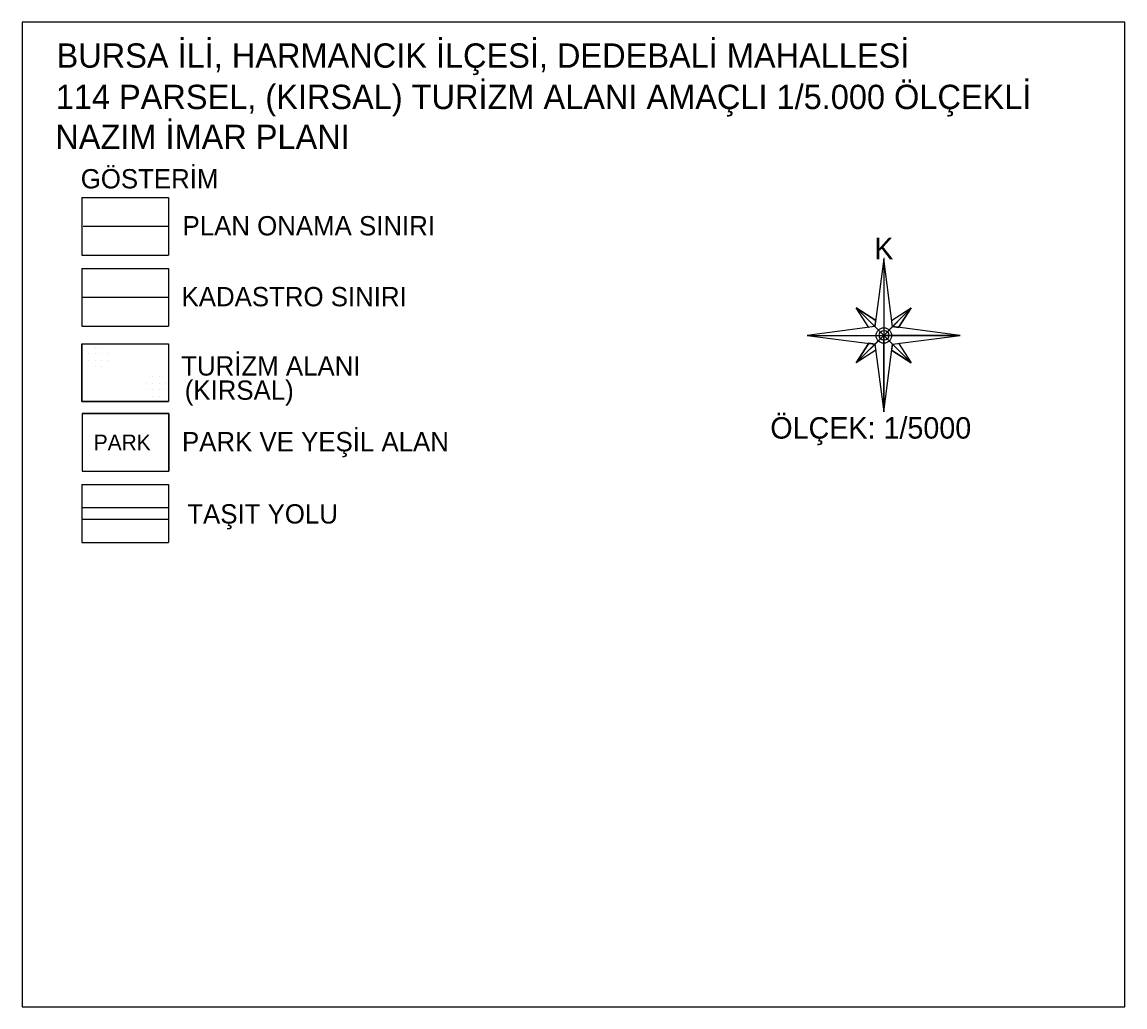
# Model space of a CAD drawing. Extents: x 415376 to 421084, y 4391163 to 4393878.
# Drawn here: x 420706.1 to 421084, y 4391162.7 to 4391500.1 of the extents above; entities that cross this region are included whole.
import ezdxf

# ---------------------------------------------------------------- set-up
doc = ezdxf.new("R2010")
doc.units = 0
for name, color, linetype in [('KALDIRIM', 7, 'Continuous'), ('LEJAND', 7, 'Continuous'), ('PL_KiRSALTURIZM', 7, 'Continuous'), ('PL_PARK', 7, 'Continuous'), ('SN_PLAN_ONAMA', 7, 'Continuous'), ('TR_TURIZM', 7, 'Continuous'), ('Z_PARSEL_PL', 7, 'Continuous')]:
    doc.layers.add(name, color=color, linetype=linetype)

msp = doc.modelspace()

# ---------------------------------------------------------------- linework, layer by layer
at = {"layer": 'KALDIRIM'}
for p, q in [((420726.6, 4391333.76), (420734.34, 4391333.76)), ((420734.34, 4391333.76), (420756.28, 4391333.76)), ((420726.6, 4391329.84), (420734.57, 4391329.84)), ((420734.57, 4391329.84), (420756.28, 4391329.84))]:
    msp.add_line(p, q, dxfattribs=at)
at = {"layer": 'LEJAND'}
for p, q in [((421084.04, 4391500.11), (420706.14, 4391500.11)), ((420706.14, 4391500.11), (420706.14, 4391162.72)), ((421084.04, 4391162.72), (421084.04, 4391500.11)), ((420726.6, 4391440.03), (420726.6, 4391420.21)), ((420726.6, 4391440.03), (420756.33, 4391440.03)), ((420756.33, 4391440.03), (420756.33, 4391420.21)), ((420726.6, 4391420.21), (420756.33, 4391420.21)), ((421001.37, 4391419.02), (421001.37, 4391392.79)), ((421001.59, 4391419.3), (421001.59, 4391419.25)), ((420726.6, 4391415.72), (420756.33, 4391415.72)), ((420726.6, 4391415.72), (420726.6, 4391395.9)), ((420756.33, 4391415.72), (420756.33, 4391395.9)), ((421001.37, 4391392.79), (420991.98, 4391402.18)), ((421001.37, 4391392.79), (421010.76, 4391402.18)), ((420726.6, 4391395.9), (420756.33, 4391395.9)), ((420726.6, 4391389.91), (420726.6, 4391370.1)), ((420726.6, 4391389.91), (420756.33, 4391389.91)), ((420756.33, 4391389.91), (420756.33, 4391370.1)), ((420975.15, 4391392.79), (421001.37, 4391392.79)), ((421001.37, 4391392.79), (420991.98, 4391383.4)), ((421001.37, 4391392.79), (421001.37, 4391366.57)), ((421001.37, 4391392.79), (421010.76, 4391383.4)), ((421001.37, 4391392.79), (421027.6, 4391392.79)), ((420726.6, 4391370.1), (420756.33, 4391370.1)), ((420726.76, 4391366.03), (420726.76, 4391346.21)), ((420726.76, 4391366.03), (420756.49, 4391366.03)), ((420756.49, 4391366.03), (420756.49, 4391346.21)), ((420726.76, 4391346.21), (420756.49, 4391346.21)), ((420726.6, 4391341.7), (420726.6, 4391321.88)), ((420726.6, 4391341.7), (420756.33, 4391341.7)), ((420756.33, 4391341.7), (420756.33, 4391321.88)), ((420726.6, 4391321.88), (420756.33, 4391321.88)), ((420706.14, 4391162.72), (421084.04, 4391162.72))]:
    msp.add_line(p, q, dxfattribs=at)
for points in [[(421004.36, 4391395.78), (421001.37, 4391419.02), (420998.39, 4391395.78), (420975.15, 4391392.79), (420998.39, 4391389.81), (421001.37, 4391366.57), (421004.36, 4391389.81), (421027.6, 4391392.79)], [(421001.37, 4391419.02), (421001.37, 4391392.79), (421004.36, 4391395.78)], [(420991.98, 4391402.18), (420998.39, 4391395.78), (420998.65, 4391397.86)], [(421004.36, 4391395.78), (421006.44, 4391395.51), (421010.76, 4391402.18)], [(420998.39, 4391395.78), (420975.17, 4391392.79), (421001.37, 4391392.79)], [(420996.31, 4391390.07), (420991.98, 4391383.4), (420998.39, 4391389.81)], [(421001.37, 4391392.79), (420998.39, 4391389.81), (421001.37, 4391366.57)], [(421001.37, 4391392.79), (421004.36, 4391389.81), (421027.6, 4391392.79)], [(421004.36, 4391389.81), (421004.09, 4391387.73), (421010.76, 4391383.4)]]:
    msp.add_lwpolyline(points, close=True, dxfattribs=at)
for points in [[(420996.31, 4391395.51), (420991.98, 4391402.18), (420998.65, 4391397.86)], [(421004.09, 4391397.86), (421010.76, 4391402.18), (421006.44, 4391395.51)], [(420998.65, 4391387.73), (420991.98, 4391383.4), (420996.31, 4391390.07)], [(421006.44, 4391390.07), (421010.76, 4391383.4), (421004.09, 4391387.73)]]:
    msp.add_lwpolyline(points, dxfattribs=at)
for centre, radius in [((421001.42, 4391392.73), 2.66), ((421001.46, 4391392.78), 1.66)]:
    msp.add_circle(centre, radius, dxfattribs=at)
at = {"layer": 'PL_KiRSALTURIZM'}
msp.add_lwpolyline([(420756.33, 4391389.91), (420756.33, 4391370.1), (420726.6, 4391370.1), (420726.6, 4391389.91)], close=True, dxfattribs=at)
at = {"layer": 'PL_PARK'}
msp.add_lwpolyline([(420756.49, 4391366.03), (420726.76, 4391366.03), (420726.76, 4391346.21), (420756.49, 4391346.21), (420756.49, 4391366.03)], dxfattribs=at)
at = {"layer": 'SN_PLAN_ONAMA'}
msp.add_line((420727.1, 4391430.23), (420756.16, 4391430.23), dxfattribs=at)
at = {"layer": 'TR_TURIZM'}
for p, q in [((420728.94, 4391386.4), (420728.94, 4391386.4)), ((420731.14, 4391388.6), (420731.14, 4391388.6)), ((420731.14, 4391386.4), (420731.14, 4391386.4)), ((420733.35, 4391388.6), (420733.35, 4391388.6)), ((420733.35, 4391386.4), (420733.35, 4391386.4)), ((420735.55, 4391386.4), (420735.55, 4391386.4)), ((420728.94, 4391384.19), (420728.94, 4391384.19)), ((420731.14, 4391384.19), (420731.14, 4391384.19)), ((420731.14, 4391381.99), (420731.14, 4391381.99)), ((420733.35, 4391384.19), (420733.35, 4391384.19)), ((420733.35, 4391381.99), (420733.35, 4391381.99)), ((420735.55, 4391384.19), (420735.55, 4391384.19)), ((420750.95, 4391378.53), (420750.95, 4391378.53)), ((420753.15, 4391378.53), (420753.15, 4391378.53)), ((420748.74, 4391376.33), (420748.74, 4391376.33)), ((420750.95, 4391376.33), (420750.95, 4391376.33)), ((420753.15, 4391376.33), (420753.15, 4391376.33)), ((420755.36, 4391376.33), (420755.36, 4391376.33)), ((420748.74, 4391374.12), (420748.74, 4391374.12)), ((420750.95, 4391374.12), (420750.95, 4391374.12)), ((420750.95, 4391371.92), (420750.95, 4391371.92)), ((420753.15, 4391374.12), (420753.15, 4391374.12)), ((420753.15, 4391371.92), (420753.15, 4391371.92)), ((420755.36, 4391374.12), (420755.36, 4391374.12))]:
    msp.add_line(p, q, dxfattribs=at)
at = {"layer": 'Z_PARSEL_PL'}
msp.add_line((420726.6, 4391405.81), (420756.33, 4391405.81), dxfattribs=at)

# ---------------------------------------------------------------- texts
at = {"layer": 'LEJAND'}
for s, height, p in [('BURSA İLİ, HARMANCIK İLÇESİ, DEDEBALİ MAHALLESİ', 8.33, (420717.97, 4391484.47)), ('114 PARSEL, (KIRSAL) TURİZM ALANI AMAÇLI 1/5.000 ÖLÇEKLİ', 8.33, (420717.68, 4391470.3)), ('NAZIM İMAR PLANI', 8.33, (420717.54, 4391456.6)), ('GÖSTERİM', 6.615, (420726.25, 4391443.12)), ('PLAN ONAMA SINIRI', 6.615, (420761.13, 4391427.02)), ('K', 7.35, (420998.11, 4391418.87)), ('KADASTRO SINIRI ', 6.615, (420760.79, 4391402.74)), ('TURİZM ALANI', 6.615, (420760.68, 4391379)), ('(KIRSAL)', 6.615, (420761.88, 4391370.71)), ('ÖLÇEK: 1/5000', 7.35, (420962.52, 4391357.41)), ('PARK VE YEŞİL ALAN', 6.615, (420760.95, 4391353.06)), ('PARK', 5.358, (420730.71, 4391353.43)), ('TAŞIT YOLU', 6.615, (420762.75, 4391328.32))]:
    msp.add_text(s, height=height, dxfattribs=at).set_placement(p)

doc.saveas('drawing.dxf')
